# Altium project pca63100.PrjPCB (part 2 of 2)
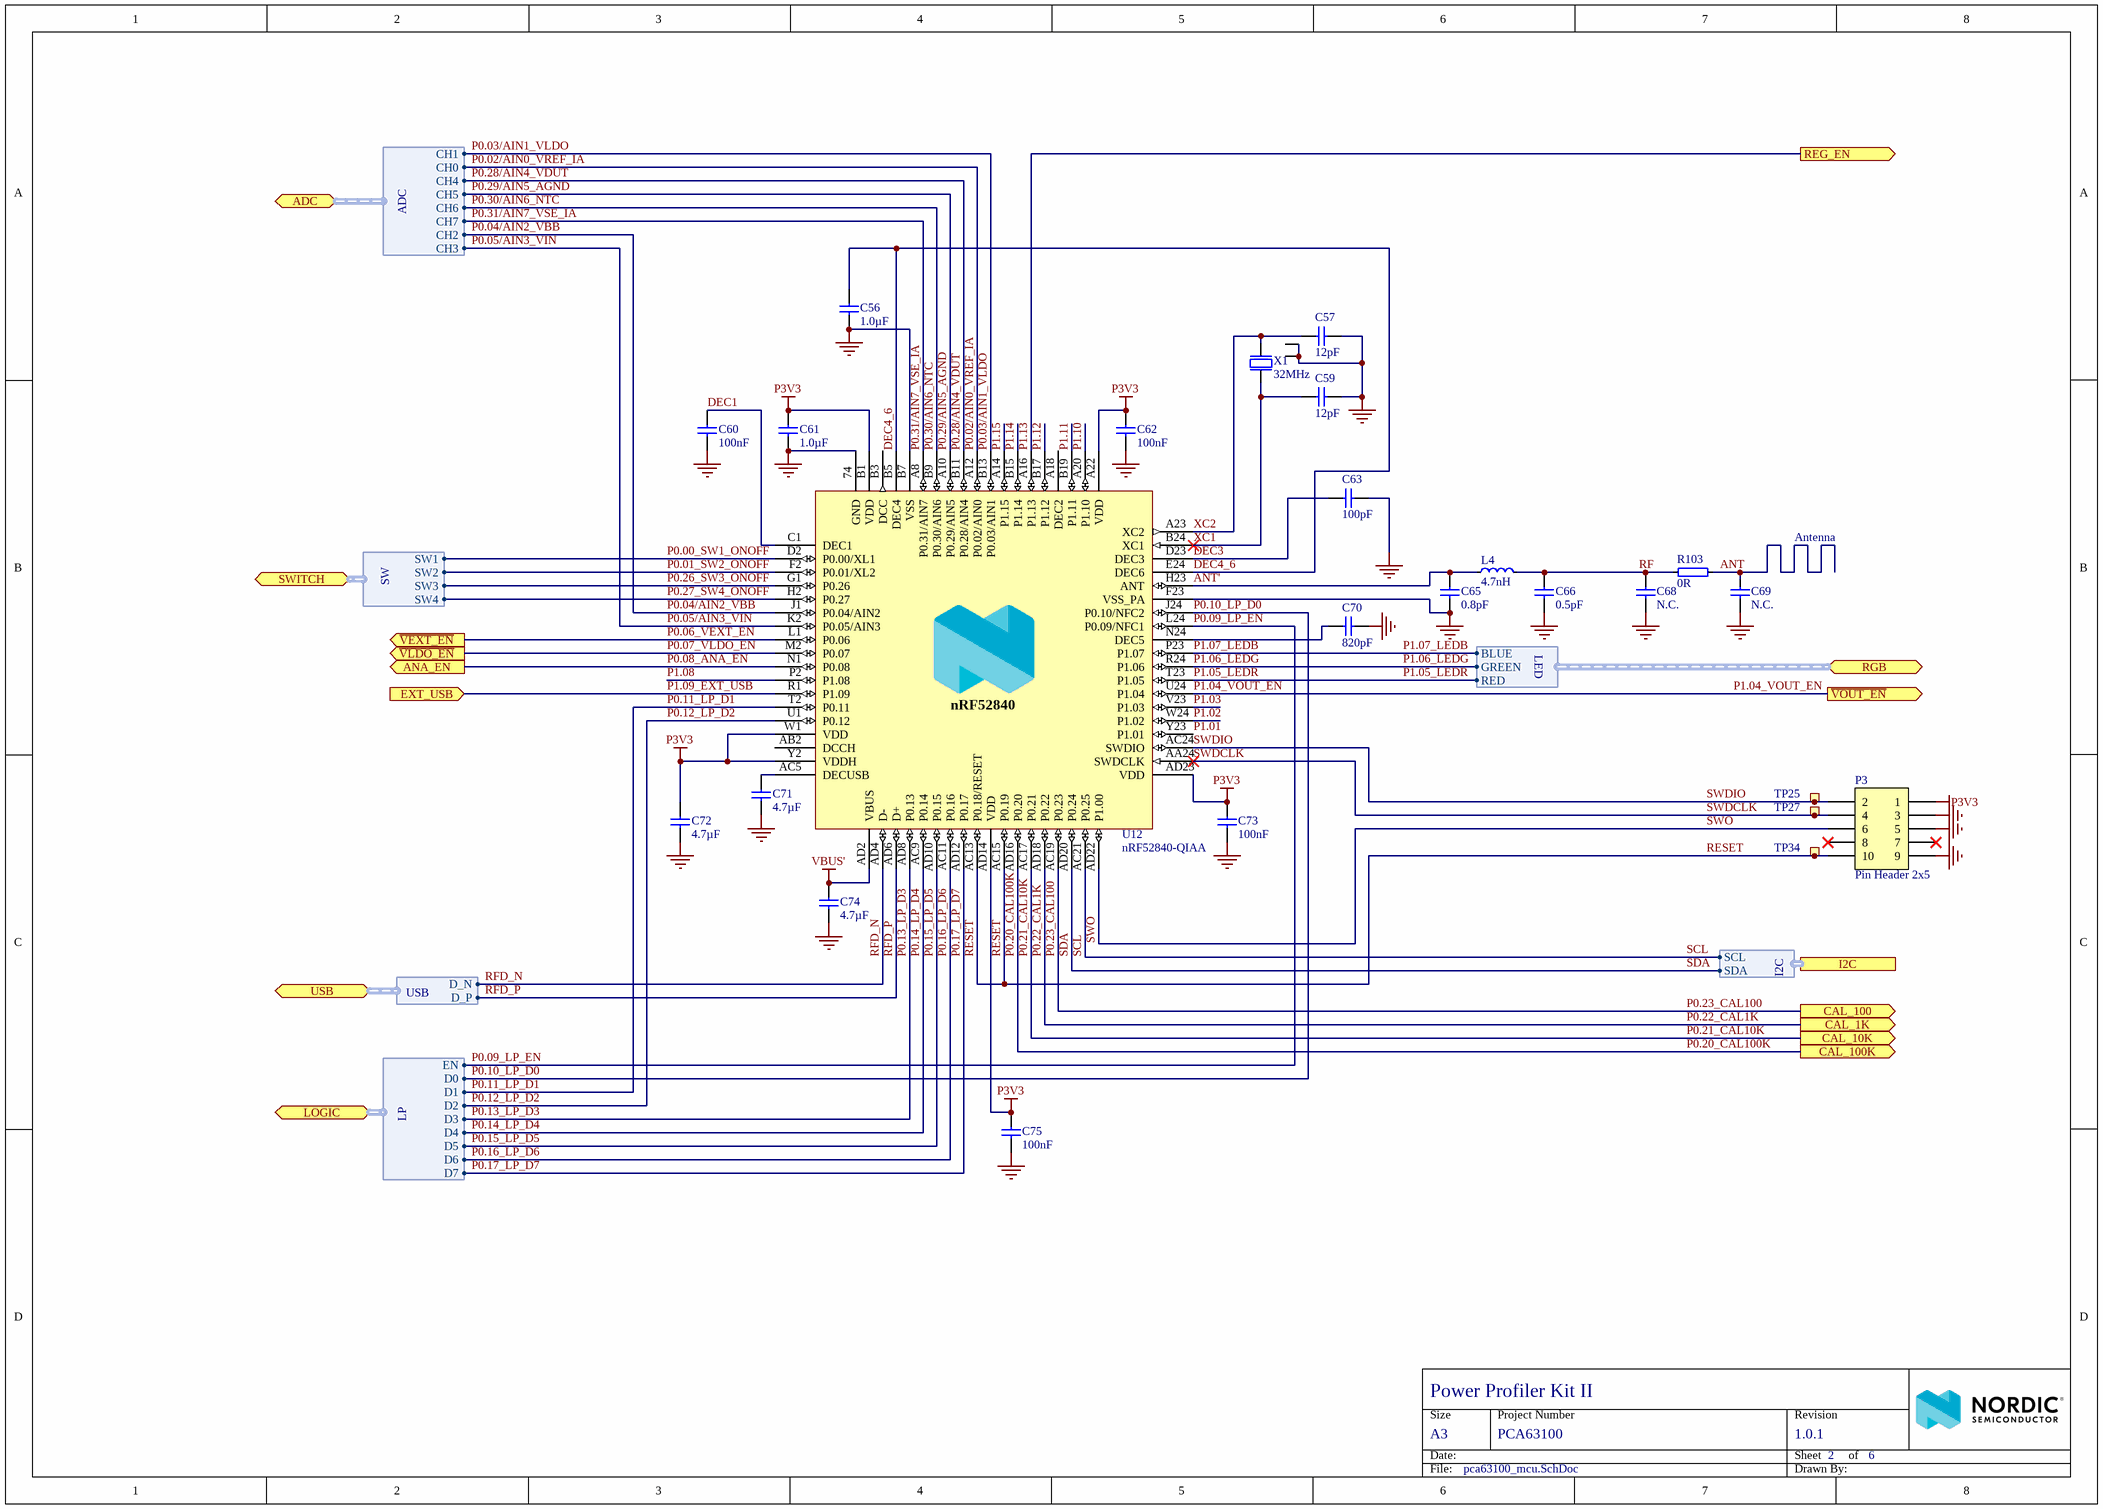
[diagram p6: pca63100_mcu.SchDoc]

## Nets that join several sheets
GND: pca63100_top (H1.1 H2.1 H3.1 H4.1), pca63100_current_automatic_switch (SB1.2 TP26.1), pca63100_current_measurement (22 pins), pca63100_power_supply (57 pins), pca63100_misc (23 pins), pca63100_mcu (25 pins)
N2V0: pca63100_current_automatic_switch (7 pins), pca63100_power_supply (C44.2 D5.2 R79.1 TP18.1)
P3V3: pca63100_current_measurement (7 pins), pca63100_power_supply (C35.2 R68.1 TP15.1 U4.1), pca63100_misc (21 pins), pca63100_mcu (12 pins)
P7V0: pca63100_current_automatic_switch (7 pins), pca63100_power_supply (5 pins)
P8V0: pca63100_current_measurement (R37.1 R104.2 R105.2), pca63100_power_supply (7 pins)
VBUS': pca63100_power_supply (9 pins), pca63100_mcu (C74.1 U12.AD2)
VDUT+: pca63100_current_automatic_switch (R22.2 TP5.1), pca63100_current_measurement (11 pins), pca63100_power_supply (R34.2), pca63100_misc (SB3.1)
VDUT-: pca63100_current_automatic_switch (R19.2 TP2.1), pca63100_current_measurement (17 pins)
VLDO: pca63100_current_measurement (Q16.4 Q16.6), pca63100_power_supply (7 pins)
AUTO_SW1: pca63100_current_automatic_switch (R15.2 R21.2 U2.15), pca63100_current_measurement (R44.1 R45.2)
AUTO_SW2: pca63100_current_automatic_switch (R13.1 R24.2 R26.2 U2.6), pca63100_current_measurement (R48.1 R49.2)
AUTO_SW3: pca63100_current_automatic_switch (R23.1 R28.2 R30.2 U2.7), pca63100_current_measurement (R52.1 R53.2)
AUTO_SW4: pca63100_current_automatic_switch (R27.1 R32.2 U2.14), pca63100_current_measurement (R56.1 R57.2)
P0.00_SW1_ONOFF: pca63100_current_measurement (Q6.6 R43.1 TP30.1), pca63100_mcu (U12.D2)
P0.01_SW2_ONOFF: pca63100_current_measurement (Q6.3 R47.1 TP31.1), pca63100_mcu (U12.F2)
P0.02/AIN0_VREF_IA: pca63100_current_automatic_switch (C6.1 R10.1 U1.1 U1.15), pca63100_mcu (U12.A12)
P0.03/AIN1_VLDO: pca63100_power_supply (R90.1 R92.2), pca63100_mcu (U12.B13)
P0.04/AIN2_VBB: pca63100_power_supply (R16.1 R91.2), pca63100_mcu (U12.J1)
P0.05/AIN3_VIN: pca63100_power_supply (R110.1 R111.2), pca63100_mcu (U12.K2)
P0.06_VEXT_EN: pca63100_current_measurement (Q17.2 R106.1 TP40.1), pca63100_mcu (U12.L1)
P0.07_VLDO_EN: pca63100_current_measurement (Q17.5 R107.1 TP41.1), pca63100_mcu (U12.M2)
P0.08_ANA_EN: pca63100_power_supply (R68.2 U5.C1), pca63100_mcu (U12.N1)
P0.09_LP_EN: pca63100_misc (R102.1 U11.11), pca63100_mcu (U12.L24)
P0.10_LP_D0: pca63100_misc (U11.9), pca63100_mcu (U12.J24)
P0.11_LP_D1: pca63100_misc (U11.8), pca63100_mcu (U12.T2)
P0.12_LP_D2: pca63100_misc (U11.7), pca63100_mcu (U12.U1)
P0.13_LP_D3: pca63100_misc (U11.6), pca63100_mcu (U12.AD8)
P0.14_LP_D4: pca63100_misc (U11.5), pca63100_mcu (U12.AC9)
P0.15_LP_D5: pca63100_misc (U11.4), pca63100_mcu (U12.AD10)
P0.16_LP_D6: pca63100_misc (U11.3), pca63100_mcu (U12.AC11)
P0.17_LP_D7: pca63100_misc (U11.2), pca63100_mcu (U12.AD12)
P0.20_CAL100K: pca63100_current_measurement (Q4.2 R59.2), pca63100_mcu (U12.AD16)
P0.21_CAL10K: pca63100_current_measurement (Q4.5 R35.2), pca63100_mcu (U12.AC17)
P0.22_CAL1K: pca63100_current_measurement (Q11.2 R109.2), pca63100_mcu (U12.AD18)
P0.23_CAL100: pca63100_current_measurement (Q11.5 R108.2), pca63100_mcu (U12.AC19)
P0.26_SW3_ONOFF: pca63100_current_measurement (Q8.6 R51.1 TP32.1), pca63100_mcu (U12.G1)
P0.27_SW4_ONOFF: pca63100_current_measurement (Q8.3 R55.1 TP33.1), pca63100_mcu (U12.H2)
P0.28/AIN4_VDUT: pca63100_power_supply (R34.1 R36.2), pca63100_mcu (U12.B11)
P0.29/AIN5_AGND: pca63100_current_automatic_switch (SB2.1 TP10.1), pca63100_mcu (U12.A10)
P0.30/AIN6_NTC: pca63100_misc (R72.1 R113.2), pca63100_mcu (U12.B9)
P0.31/AIN7_VSE_IA: pca63100_current_automatic_switch (C8.2 R8.2 R9.2 TP1.1), pca63100_mcu (U12.A8)
P1.04_VOUT_EN: pca63100_current_measurement (Q1.2 R39.1), pca63100_mcu (U12.U24)
P1.05_LEDR: pca63100_misc (Q15.5 R99.2), pca63100_mcu (U12.T23)
P1.06_LEDG: pca63100_misc (Q15.2 R100.2), pca63100_mcu (U12.R24)
P1.07_LEDB: pca63100_misc (Q1.5 R101.2), pca63100_mcu (U12.P23)
P1.09_EXT_USB: pca63100_power_supply (R17.2 R18.2), pca63100_mcu (U12.R1)
P1.13: pca63100_power_supply (U8.6 U9.1), pca63100_mcu (U12.A16)
POT0: pca63100_power_supply (R112.2), pca63100_misc (TP24.1 U10.10)
POT1: pca63100_power_supply (R14.2), pca63100_misc (TP23.1 U10.7)
POT3: pca63100_current_automatic_switch (U1.2), pca63100_misc (TP21.1 U10.20)
RFD_N: pca63100_power_supply (D3.3 J2.2 TP13.1), pca63100_mcu (U12.AD4)
RFD_P: pca63100_power_supply (D3.2 J2.3 TP14.1), pca63100_mcu (U12.AD6)
SCL: pca63100_misc (R82.1 U7.1 U10.3), pca63100_mcu (U12.AC21)
SDA: pca63100_misc (R81.1 U7.3 U10.4), pca63100_mcu (U12.AD20)

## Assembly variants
Default Assembly: not fitted A1 C1 C4 C6 C29 C33 C58 C64 C65 C66 C68 C69 L4 L5 LD5 LD6 P3 P3 R63 R70 R103 R115 R117 R118 R119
